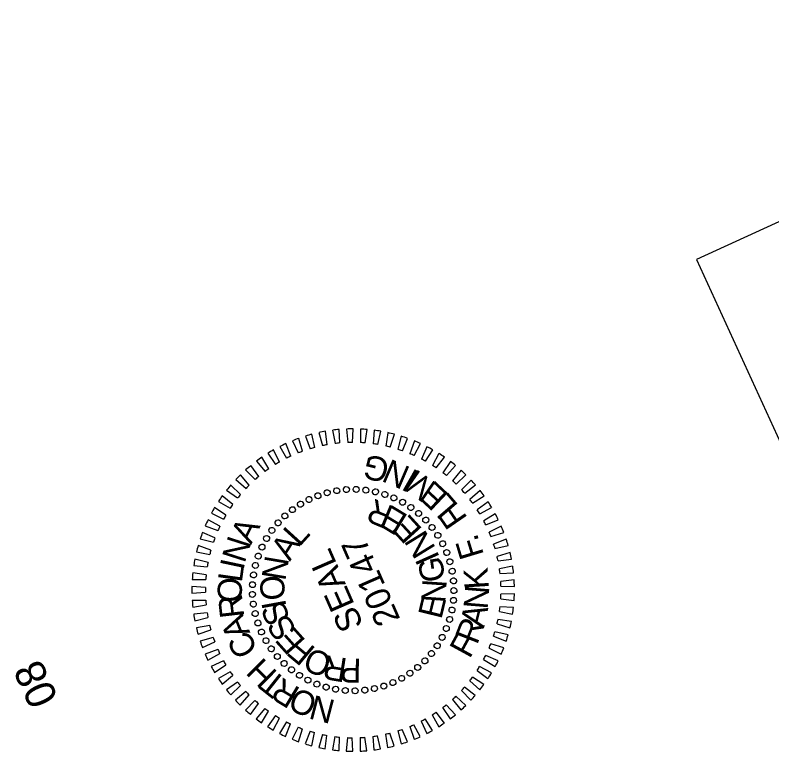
# Model space of a CAD drawing. Extents: x 2047210 to 2048779, y 758833 to 761037.
# Drawn here: x 2047210.5 to 2047398.2, y 760562.6 to 760748.1 of the extents above; entities that cross this region are included whole.
import ezdxf

# ---------------------------------------------------------------- set-up
doc = ezdxf.new("R2010")
doc.units = 0
for name, color, linetype in [('Sheet Clip Boundary CELL', 7, 'Continuous'), ('Sheet Data Field CELL', 7, 'Continuous'), ('Sheet PE Seal Cell', 7, 'Continuous')]:
    doc.layers.add(name, color=color, linetype=linetype)

msp = doc.modelspace()

# ---------------------------------------------------------------- linework, layer by layer
at = {"layer": 'Sheet Clip Boundary CELL'}
msp.add_lwpolyline([(2047755.44, 759358.92), (2048711.82, 759792.27), (2048141.81, 761036.68), (2047379.48, 760687.47), (2047474.96, 760479.04), (2047373.07, 760432.36), (2047438.89, 760288.66), (2047348.51, 760247.26)], close=True, dxfattribs=at)
at = {"layer": 'Sheet PE Seal Cell'}
for p, q in [((2047285.84, 760644.56), (2047286.73, 760641.33)), ((2047287.86, 760641.55), (2047287.46, 760644.88)), ((2047289.23, 760645.15), (2047289.84, 760641.85)), ((2047290.98, 760641.97), (2047290.87, 760645.32)), ((2047292.66, 760645.44), (2047292.98, 760642.1)), ((2047294.13, 760642.12), (2047294.31, 760645.47)), ((2047296.1, 760645.43), (2047296.14, 760642.08)), ((2047297.28, 760642), (2047297.75, 760645.32)), ((2047299.53, 760645.13), (2047299.28, 760641.78)), ((2047300.41, 760641.61), (2047301.16, 760644.88)), ((2047302.92, 760644.53), (2047302.38, 760641.22)), ((2047279.27, 760642.53), (2047280.7, 760639.5)), ((2047281.77, 760639.91), (2047280.81, 760643.12)), ((2047282.51, 760643.69), (2047283.67, 760640.54)), ((2047284.78, 760640.86), (2047284.1, 760644.14)), ((2047303.5, 760640.95), (2047304.53, 760644.14)), ((2047306.25, 760643.65), (2047305.42, 760640.4)), ((2047306.51, 760640.03), (2047307.81, 760643.12)), ((2047309.49, 760642.48), (2047308.38, 760639.31)), ((2047276.14, 760641.1), (2047277.82, 760638.2)), ((2047278.86, 760638.7), (2047277.63, 760641.82)), ((2047309.44, 760638.85), (2047311, 760641.82)), ((2047312.61, 760641.04), (2047311.24, 760637.98)), ((2047273.14, 760639.41), (2047275.07, 760636.66)), ((2047276.06, 760637.25), (2047274.56, 760640.25)), ((2047312.25, 760637.43), (2047314.06, 760640.26)), ((2047315.6, 760639.34), (2047313.97, 760636.4)), ((2047270.31, 760637.46), (2047272.46, 760634.89)), ((2047273.39, 760635.56), (2047271.65, 760638.43)), ((2047314.93, 760635.77), (2047316.98, 760638.43)), ((2047318.44, 760637.38), (2047316.56, 760634.6)), ((2047267.64, 760635.28), (2047270.01, 760632.9)), ((2047270.89, 760633.65), (2047268.9, 760636.35)), ((2047317.46, 760633.89), (2047319.73, 760636.36)), ((2047321.09, 760635.19), (2047318.98, 760632.58)), ((2047268.55, 760631.53), (2047266.34, 760634.06)), ((2047319.82, 760631.79), (2047322.29, 760634.06)), ((2047266.4, 760629.22), (2047263.98, 760631.54)), ((2047265.18, 760632.88), (2047267.74, 760630.71)), ((2047323.54, 760632.78), (2047321.22, 760630.36)), ((2047321.99, 760629.5), (2047324.65, 760631.55)), ((2047262.93, 760630.27), (2047265.67, 760628.34)), ((2047325.78, 760630.16), (2047323.26, 760627.95)), ((2047260.92, 760627.48), (2047263.81, 760625.79)), ((2047264.47, 760626.74), (2047261.85, 760628.84)), ((2047323.95, 760627.03), (2047326.78, 760628.84)), ((2047327.79, 760627.37), (2047325.09, 760625.38)), ((2047262.75, 760624.09), (2047259.96, 760625.96)), ((2047325.69, 760624.41), (2047328.66, 760625.97)), ((2047259.15, 760624.53), (2047262.18, 760623.09)), ((2047329.55, 760624.41), (2047326.68, 760622.66)), ((2047261.26, 760621.31), (2047258.33, 760622.93)), ((2047327.21, 760621.64), (2047330.3, 760622.94)), ((2047257.64, 760621.44), (2047260.78, 760620.26)), ((2047331.05, 760621.31), (2047328.04, 760619.82)), ((2047256.4, 760618.22), (2047259.64, 760617.33)), ((2047260.03, 760618.41), (2047256.96, 760619.78)), ((2047328.47, 760618.75), (2047331.67, 760619.78)), ((2047332.27, 760618.09), (2047329.15, 760616.86)), ((2047259.04, 760615.41), (2047255.87, 760616.51)), ((2047329.49, 760615.77), (2047332.76, 760616.52)), ((2047255.45, 760614.92), (2047258.75, 760614.3)), ((2047333.22, 760614.78), (2047330, 760613.83)), ((2047258.32, 760612.34), (2047255.06, 760613.17)), ((2047330.24, 760612.7), (2047333.57, 760613.17)), ((2047254.78, 760611.54), (2047258.12, 760611.21)), ((2047333.87, 760611.4), (2047330.59, 760610.73)), ((2047257.86, 760609.22), (2047254.55, 760609.76)), ((2047330.73, 760609.59), (2047334.08, 760609.77)), ((2047254.4, 760608.12), (2047257.76, 760608.08)), ((2047334.24, 760607.98), (2047330.9, 760607.59)), ((2047257.67, 760606.08), (2047254.32, 760606.33)), ((2047254.32, 760604.68), (2047257.67, 760604.93)), ((2047294.32, 760605.47), (2047294.32, 760605.47)), ((2047330.95, 760606.44), (2047334.31, 760606.33)), ((2047257.75, 760602.92), (2047254.4, 760602.89)), ((2047330.9, 760603.29), (2047334.23, 760602.89)), ((2047334.3, 760604.54), (2047330.95, 760604.44)), ((2047254.54, 760601.24), (2047257.85, 760601.78)), ((2047334.08, 760601.11), (2047330.73, 760601.29)), ((2047258.11, 760599.79), (2047254.77, 760599.47)), ((2047330.58, 760600.15), (2047333.86, 760599.47)), ((2047255.05, 760597.84), (2047258.3, 760598.66)), ((2047333.55, 760597.7), (2047330.23, 760598.18)), ((2047258.73, 760596.7), (2047255.43, 760596.09)), ((2047255.85, 760594.49), (2047259.02, 760595.59)), ((2047329.99, 760597.05), (2047333.2, 760596.09)), ((2047259.62, 760593.67), (2047256.38, 760592.78)), ((2047329.13, 760594.02), (2047332.25, 760592.79)), ((2047332.74, 760594.36), (2047329.47, 760595.12)), ((2047256.94, 760591.23), (2047260, 760592.59)), ((2047331.64, 760591.1), (2047328.45, 760592.13)), ((2047260.76, 760590.73), (2047257.61, 760589.57)), ((2047328.02, 760591.07), (2047331.02, 760589.57)), ((2047258.3, 760588.07), (2047261.24, 760589.69)), ((2047262.15, 760587.9), (2047259.12, 760586.47)), ((2047326.65, 760588.22), (2047329.52, 760586.47)), ((2047330.27, 760587.94), (2047327.18, 760589.25)), ((2047259.93, 760585.03), (2047262.72, 760586.9)), ((2047328.63, 760584.92), (2047325.66, 760586.48)), ((2047263.78, 760585.2), (2047260.88, 760583.51)), ((2047261.81, 760582.15), (2047264.43, 760584.25)), ((2047325.05, 760585.51), (2047327.75, 760583.52)), ((2047265.64, 760582.65), (2047262.89, 760580.72)), ((2047323.22, 760582.94), (2047325.74, 760580.73)), ((2047326.74, 760582.04), (2047323.92, 760583.86)), ((2047263.94, 760579.45), (2047266.37, 760581.76)), ((2047321.18, 760580.54), (2047323.5, 760578.12)), ((2047324.6, 760579.34), (2047321.95, 760581.39)), ((2047267.7, 760580.27), (2047265.13, 760578.11)), ((2047266.29, 760576.93), (2047268.51, 760579.45)), ((2047322.24, 760576.84), (2047319.78, 760579.11)), ((2047269.97, 760578.08), (2047267.59, 760575.7)), ((2047268.85, 760574.63), (2047270.84, 760577.33)), ((2047319.68, 760574.54), (2047317.42, 760577.02)), ((2047318.94, 760578.32), (2047321.04, 760575.71)), ((2047272.41, 760576.09), (2047270.25, 760573.52)), ((2047271.59, 760572.55), (2047273.35, 760575.41)), ((2047316.93, 760572.47), (2047314.88, 760575.14)), ((2047316.51, 760576.31), (2047318.38, 760573.52)), ((2047275.02, 760574.31), (2047273.09, 760571.57)), ((2047274.5, 760570.72), (2047276.01, 760573.72)), ((2047311.19, 760572.93), (2047312.55, 760569.87)), ((2047314.01, 760570.65), (2047312.2, 760573.48)), ((2047313.92, 760574.51), (2047315.55, 760571.57)), ((2047277.77, 760572.77), (2047276.08, 760569.87)), ((2047277.57, 760569.15), (2047278.8, 760572.26)), ((2047280.64, 760571.47), (2047279.21, 760568.43)), ((2047280.75, 760567.84), (2047281.72, 760571.05)), ((2047308.33, 760571.6), (2047309.43, 760568.43)), ((2047310.94, 760569.09), (2047309.38, 760572.06)), ((2047283.62, 760570.42), (2047282.45, 760567.27)), ((2047284.03, 760566.81), (2047284.72, 760570.1)), ((2047286.67, 760569.63), (2047285.78, 760566.39)), ((2047287.4, 760566.07), (2047287.8, 760569.4)), ((2047299.22, 760569.15), (2047299.47, 760565.8)), ((2047301.1, 760566.05), (2047300.35, 760569.32)), ((2047302.32, 760569.71), (2047302.86, 760566.39)), ((2047304.46, 760566.78), (2047303.44, 760569.97)), ((2047305.36, 760570.53), (2047306.19, 760567.27)), ((2047307.75, 760567.79), (2047306.46, 760570.89)), ((2047289.78, 760569.1), (2047289.17, 760565.8)), ((2047290.81, 760565.62), (2047290.92, 760568.98)), ((2047292.92, 760568.85), (2047292.6, 760565.51)), ((2047294.25, 760565.47), (2047294.07, 760568.82)), ((2047296.08, 760568.86), (2047296.04, 760565.51)), ((2047297.69, 760565.61), (2047297.22, 760568.94))]:
    msp.add_line(p, q, dxfattribs=at)
for radius, start, end in [(40, 99.8668, 102.2304), (40, 94.9353, 97.2989), (40, 90.0038, 92.3674), (40, 85.0722, 87.4359), (40, 80.1407, 82.5044), (40, 75.2092, 77.5729), (40, 109.7298, 112.0934), (40, 104.7983, 107.1619), (40, 70.2777, 72.6413), (40, 65.3462, 67.7098), (40, 114.6613, 117.0249), (36.65, 105.0811, 106.879), (36.65, 100.1496, 101.9475), (36.65, 95.2181, 97.016), (36.65, 90.2866, 92.0845), (36.65, 85.3551, 87.153), (36.65, 80.4236, 82.2215), (36.65, 75.4921, 77.29), (40, 60.4147, 62.7783), (40, 119.5928, 121.9564), (36.65, 114.9442, 116.742), (36.65, 110.0126, 111.8105), (36.65, 70.5606, 72.3585), (36.65, 65.6291, 67.427), (40, 55.4832, 57.8468), (40, 124.5243, 126.8879), (36.65, 119.8757, 121.6736), (36.65, 60.6976, 62.4955), (40, 50.5517, 52.9153), (40, 129.4558, 131.8194), (36.65, 124.8072, 126.6051), (36.65, 55.7661, 57.564), (40, 45.6202, 47.9838), (40, 134.3873, 136.7509), (36.65, 129.7387, 131.5366), (36.65, 50.8346, 52.6325), (40, 139.3188, 141.6824), (36.65, 134.6702, 136.4681), (36.65, 45.9031, 47.701), (40, 40.6887, 43.0523), (36.65, 139.6017, 141.3996), (36.65, 40.9716, 42.7694), (40, 35.7572, 38.1208), (40, 144.2503, 146.614), (36.65, 36.04, 37.8379), (40, 30.8257, 33.1893), (40, 149.1818, 151.5455), (36.65, 144.5332, 146.3311), (36.65, 149.4647, 151.2626), (36.65, 31.1085, 32.9064), (40, 25.8942, 28.2578), (40, 154.1133, 156.477), (36.65, 26.177, 27.9749), (36.65, 154.3962, 156.1941), (36.65, 21.2455, 23.0434), (40, 20.9627, 23.3263), (40, 159.0449, 161.4085), (36.65, 159.3277, 161.1256), (40, 16.0312, 18.3948), (40, 163.9764, 166.34), (36.65, 16.314, 18.1119), (36.65, 164.2592, 166.0571), (40, 11.0996, 13.4633), (40, 168.9079, 171.2715), (36.65, 169.1907, 170.9886), (36.65, 11.3825, 13.1804), (36.65, 6.451, 8.2489), (40, 6.1681, 8.5318), (40, 173.8394, 176.203), (36.65, 174.1222, 175.9201), (36.65, 1.5195, 3.3174), (40, 1.2366, 3.6003), (40, 178.7709, 181.1345), (36.65, 179.0537, 180.8516), (36.65, 183.9852, 185.7831), (36.65, 356.588, 358.3859), (40, 356.3051, 358.6687), (40, 183.7024, 186.066), (36.65, 351.6565, 353.4544), (40, 351.3736, 353.7372), (40, 188.6339, 190.9975), (36.65, 188.9168, 190.7147), (36.65, 346.725, 348.5229), (40, 346.4421, 348.8057), (40, 193.5654, 195.929), (36.65, 193.8483, 195.6462), (36.65, 198.7798, 200.5777), (36.65, 341.7935, 343.5914), (40, 341.5106, 343.8742), (40, 198.4969, 200.8605), (36.65, 336.862, 338.6599), (36.65, 203.7113, 205.5092), (40, 336.5791, 338.9427), (40, 203.4284, 205.792), (36.65, 208.6428, 210.4407), (36.65, 331.9305, 333.7283), (40, 331.6476, 334.0112), (40, 208.3599, 210.7235), (36.65, 326.9989, 328.7968), (36.65, 213.5743, 215.3722), (40, 326.7161, 329.0797), (40, 213.2914, 215.655), (36.65, 218.5058, 220.3037), (36.65, 322.0674, 323.8653), (40, 218.2229, 220.5866), (36.65, 317.1359, 318.9338), (40, 321.7846, 324.1482), (36.65, 223.4373, 225.2352), (36.65, 312.2044, 314.0023), (40, 316.8531, 319.2167), (40, 223.1544, 225.5181), (36.65, 228.3688, 230.1667), (36.65, 307.2729, 309.0708), (40, 311.9216, 314.2852), (40, 228.0859, 230.4496), (36.65, 233.3003, 235.0982), (36.65, 302.3414, 304.1393), (40, 233.0175, 235.3811), (36.65, 238.2318, 240.0297), (36.65, 297.4099, 299.2078), (40, 306.9901, 309.3537), (40, 237.949, 240.3126), (36.65, 243.1633, 244.9612), (36.65, 248.0948, 249.8927), (36.65, 292.4784, 294.2763), (40, 302.0586, 304.4222), (40, 242.8805, 245.2441), (36.65, 253.0263, 254.8242), (36.65, 257.9579, 259.7557), (36.65, 277.6839, 279.4818), (36.65, 282.6154, 284.4133), (36.65, 287.5469, 289.3448), (40, 297.127, 299.4907), (40, 247.812, 250.1756), (40, 252.7435, 255.1071), (36.65, 262.8894, 264.6873), (36.65, 267.8209, 269.6188), (36.65, 272.7524, 274.5503), (40, 287.264, 289.6276), (40, 292.1955, 294.5592), (40, 257.675, 260.0386), (40, 262.6065, 264.9701), (40, 267.538, 269.9016), (40, 272.4695, 274.8331), (40, 277.401, 279.7646), (40, 282.3325, 284.6961)]:
    msp.add_arc((2047294.32, 760605.47), radius, start, end, dxfattribs=at)
for centre, major_axis in [((2047292.64, 760630.41), (-0.101, 0.735)), ((2047295.06, 760630.46), (-0.03, 0.742)), ((2047285.58, 760628.89), (-0.307, 0.676)), ((2047287.88, 760629.63), (-0.241, 0.702)), ((2047290.24, 760630.14), (-0.172, 0.722)), ((2047297.46, 760630.27), (0.042, 0.741)), ((2047299.84, 760629.85), (0.113, 0.734)), ((2047302.17, 760629.2), (0.184, 0.719)), ((2047304.42, 760628.34), (0.252, 0.698)), ((2047281.24, 760626.78), (-0.431, 0.604)), ((2047283.36, 760627.94), (-0.371, 0.643)), ((2047306.58, 760627.25), (0.318, 0.671)), ((2047279.24, 760625.42), (-0.488, 0.56)), ((2047308.63, 760625.97), (0.382, 0.637)), ((2047277.39, 760623.87), (-0.539, 0.51)), ((2047310.54, 760624.49), (0.441, 0.597)), ((2047312.3, 760622.84), (0.497, 0.552)), ((2047275.69, 760622.15), (-0.586, 0.456)), ((2047313.89, 760621.02), (0.548, 0.501)), ((2047274.17, 760620.28), (-0.627, 0.397)), ((2047315.3, 760619.06), (0.593, 0.446)), ((2047272.84, 760618.26), (-0.663, 0.334)), ((2047271.7, 760616.13), (-0.692, 0.269)), ((2047316.51, 760616.97), (0.634, 0.387)), ((2047270.78, 760613.9), (-0.715, 0.201)), ((2047317.52, 760614.77), (0.668, 0.324)), ((2047270.07, 760611.59), (-0.731, 0.131)), ((2047318.31, 760612.49), (0.696, 0.258)), ((2047318.88, 760610.14), (0.718, 0.189)), ((2047269.6, 760609.22), (-0.74, 0.06)), ((2047319.21, 760607.75), (0.733, 0.119)), ((2047269.35, 760606.81), (-0.742, -0.012)), ((2047269.34, 760604.4), (-0.738, -0.083)), ((2047319.31, 760605.33), (0.741, 0.048)), ((2047319.19, 760602.92), (0.742, -0.024)), ((2047269.56, 760601.99), (-0.726, -0.154)), ((2047318.82, 760600.53), (0.736, -0.095)), ((2047270.01, 760599.62), (-0.708, -0.224)), ((2047270.69, 760597.3), (-0.683, -0.291)), ((2047318.23, 760598.19), (0.724, -0.166)), ((2047271.59, 760595.06), (-0.652, -0.355)), ((2047317.42, 760595.92), (0.704, -0.235)), ((2047272.7, 760592.91), (-0.614, -0.417)), ((2047316.39, 760593.73), (0.678, -0.302)), ((2047274.01, 760590.89), (-0.571, -0.474)), ((2047315.15, 760591.66), (0.646, -0.366)), ((2047275.51, 760588.99), (-0.523, -0.527)), ((2047313.72, 760589.71), (0.607, -0.427)), ((2047277.19, 760587.26), (-0.47, -0.575)), ((2047312.11, 760587.91), (0.563, -0.483)), ((2047279.03, 760585.69), (-0.412, -0.618)), ((2047310.33, 760586.27), (0.514, -0.535)), ((2047281.01, 760584.31), (-0.35, -0.654)), ((2047306.35, 760583.56), (0.402, -0.624)), ((2047308.4, 760584.82), (0.46, -0.583)), ((2047283.11, 760583.12), (-0.286, -0.685)), ((2047285.32, 760582.14), (-0.218, -0.71)), ((2047301.91, 760581.65), (0.274, -0.69)), ((2047304.17, 760582.5), (0.34, -0.66)), ((2047287.62, 760581.38), (-0.149, -0.727)), ((2047289.97, 760580.85), (-0.078, -0.738)), ((2047292.37, 760580.55), (-0.006, -0.742)), ((2047294.78, 760580.47), (0.066, -0.739)), ((2047297.19, 760580.64), (0.137, -0.73)), ((2047299.58, 760581.03), (0.206, -0.713))]:
    msp.add_ellipse(centre, major_axis=major_axis, ratio=0.999708, dxfattribs=at)

# ---------------------------------------------------------------- texts
at = {"layer": 'Sheet Data Field CELL'}
msp.add_text('08', height=7.5, rotation=114.5739, dxfattribs=at).set_placement((2047221.3, 760578.57))
at = {"layer": 'Sheet PE Seal Cell'}
for s, height, rotation, p in [('G', 6, 166.0582, (2047303.7, 760637.77)), ('N', 6, 156.7219, (2047308.79, 760635.83)), ('I', 6, 150.3664, (2047310.88, 760634.72)), ('M', 6, 145.4202, (2047315.29, 760631.84)), ('E', 6, 136.7779, (2047318.27, 760629.1)), ('L', 6, 130.6615, (2047320.61, 760626.46)), ('R', 6, 157.6079, (2047304.7, 760626.07)), ('E', 6, 148.8549, (2047308.2, 760623.92)), ('F', 6, 124.6218, (2047322.83, 760623.35)), ('E', 6, 132.4512, (2047311.68, 760620.55)), ('A', 6, 63.2869, (2047269.02, 760616.65)), ('L', 6, 47.6989, (2047280.93, 760616.02)), ('N', 6, 121.602, (2047314.93, 760615.86)), ('N', 6, 72.2172, (2047267.39, 760611.95)), ('A', 6, 57.832, (2047278.63, 760612.45)), ('.', 6, 105.1686, (2047325.57, 760617.62)), ('20147', 6.185, 113.6102, (2047306.07, 760598.25)), ('F', 6, 106.8043, (2047326.79, 760614.23)), ('SEAL', 6.184, 113.6102, (2047296.96, 760596.82)), ('I', 6, 114.1525, (2047315.88, 760613.53)), ('I', 6, 78.0537, (2047267.1, 760610.24)), ('N', 6, 80.3523, (2047277.47, 760607.59)), ('G', 6, 98.5678, (2047317.18, 760607.91)), ('L', 6, 82.0413, (2047266.68, 760607.19)), ('K', 6, 93.6412, (2047327.98, 760605.84)), ('O', 6, 92.0658, (2047277.4, 760602.99)), ('O', 6, 89.2416, (2047266.68, 760602.35)), ('N', 6, 86.0381, (2047317.14, 760602.14)), ('N', 6, 85.2668, (2047327.64, 760600.56)), ('R', 6, 96.5309, (2047267.34, 760598.85)), ('E', 6, 76.1846, (2047316.16, 760598.03)), ('I', 6, 100.4557, (2047277.8, 760601.34)), ('S', 6, 114.6156, (2047278.88, 760598.45)), ('A', 6, 76.0271, (2047326.57, 760595.86)), ('A', 6, 112.0181, (2047268.84, 760594.89)), ('S', 6, 122.9958, (2047280.54, 760595.47)), ('R', 6, 68.5791, (2047325.03, 760591.71)), ('E', 6, 131.7949, (2047282.75, 760592.9)), ('C', 6, 120.9025, (2047270.92, 760590.83)), ('F', 6, 61.3717, (2047323.21, 760588.24)), ('F', 6, 140.0221, (2047285.27, 760590.91)), ('O', 6, 158.9698, (2047289.47, 760589.14)), ('H', 6, 135.2714, (2047275.77, 760584.97)), ('R', 6, 170.8961, (2047293.11, 760588.45)), ('P', 6, 179.4033, (2047296.4, 760588.47)), ('T', 6, 141.6645, (2047278.18, 760583.01)), ('R', 6, 148.7615, (2047281.48, 760580.95)), ('O', 6, 156.4241, (2047285.9, 760579.02)), ('N', 6, 165.4438, (2047290.18, 760578.02))]:
    msp.add_text(s, height=height, rotation=rotation, dxfattribs=at).set_placement(p)

doc.saveas('drawing.dxf')
